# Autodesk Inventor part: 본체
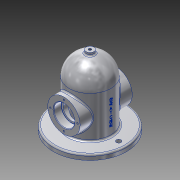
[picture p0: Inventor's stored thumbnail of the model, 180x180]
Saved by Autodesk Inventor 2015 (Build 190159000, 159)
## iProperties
Created: 2019-11
Part Number: 본체
Material: 알루미늄 6061
Document SubType Name: Modeling
Designer: 101020202
Density: 2.7 g/cm^3
Appearance: 알루미늄 - 평지
Author: 101020202
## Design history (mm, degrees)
sketch "스케치1"
  geometry: C1 r 70 at (0, 0); 1 further point
  constraints: 1 centre point, 1 coincident
  dimensions: "d0" = 140 diameter of C1
extrude "돌출1" new body sketch "스케치1" distance "d1" = 10; taper "d2" = 0 deg
sketch "스케치2"
  geometry: C1 r 70 at (0, 0) reference; C2 r 40 at (0, 0)
  constraints: 1 centre point, 1 coincident
  dimensions: "d3" = 80 diameter of C2
extrude "돌출2" join sketch "스케치2" distance "d4" = 120; taper "d5" = 0 deg
fillet "모깎기1" dims "d6" = 40
sketch "스케치3"
  geometry: L1 (-70, 0)-(-70, 10) reference; L2 (-70, 10)-(-40, 10) reference; L3 (-40, 10)-(-40, 90) reference; L4 (40, 90)-(40, 10) reference; L5 (40, 10)-(70, 10) reference; L6 (70, 10)-(70, 0) reference; L7 (70, 0)-(-70, 0) reference; C1 r 31 at (0, 50); A1 r 40 centre (0, 90) between (0, 130) and (-40, 90) reference; A2 r 40 centre (0, 90) between (40, 90) and (0, 130) reference; 2 further points
  constraints: 1 centre point, 1 midpoint, 1 vertical alignment
  dimensions: "d7" = 62 diameter of C1; "d8" = 50 distance of point (0, 0) C1.centre
extrude "돌출3" join sketch "스케치3" stored distance "d9" = 100; taper "d10" = 0 deg
sketch "스케치4"
  geometry: L1 (70, 10)-(70, 0) reference; L2 (70, 0)-(-70, 0) reference; L3 (-70, 0)-(-70, 10) reference; L4 (-70, 10)-(-40, 10) reference; L5 (-40, 10)-(-40, 19) reference; L6 (-40, 19)-(-50, 19) reference; L7 (-50, 19)-(-50, 81) reference; L8 (-50, 81)-(-40, 81) reference; L9 (-40, 81)-(-40, 90) reference; L10 (40, 90)-(40, 81) reference; L11 (40, 81)-(50, 81) reference; L12 (50, 81)-(50, 19) reference; L13 (50, 19)-(40, 19) reference; L14 (40, 19)-(40, 10) reference; L15 (40, 10)-(70, 10) reference; L16 (0, 0)-(30, 0); L17 (30, 0)-(30, 90); L18 (0, 120)-(0, 0); A1 r 40 centre (0, 90) between (40, 90) and (0, 130) reference; A2 r 40 centre (0, 90) between (0, 130) and (-40, 90) reference; A3 r 30 centre (0, 90) between (30, 90) and (0, 120)
  constraints: 6 end point, 2 point on circle, 1 centre point, 1 horizontal, 1 perpendicular, 1 vertical
  dimensions: "d11" = 30 radius of A3; "d12" = 10 distance between parallel lines of L10 L17; "d13" = 90 distance of L16.end L17.end; "d14" = 120 distance of L18.start L16.start
revolve "회전1" sketch "스케치4" stored, may be unused: angle "d15" = 90 deg
sketch "스케치5"
  geometry: C1 r 31 at (0, 0) reference; 1 further point
hole "구멍1" sketch "스케치5" at (0, 0) diameter "d16" = 33; stored, may be unused: countersink angle "d20" = 90 deg, drill point angle "d22" = 0 deg; dims "d17" = 6, "d18" = 40, "d19" = 15, "d21" = 40
sketch "스케치6"
  geometry: C1 r 20 at (0, 0) reference; 2 further points
  constraints: 1 vertical alignment
  dimensions: "d23" = 26 distance of C1.centre point (0, 26)
hole "구멍2" sketch "스케치6" at (0, 26) diameter "d24" = 3.242; stored, may be unused: countersink angle "d28" = 90 deg, drill point angle "d30" = 118 deg; dims "d25" = 8, "d26" = 40, "d27" = 15, "d29" = 10
node "작업 평면1"
sketch "스케치7"
  geometry: C1 r 7.5 at (0, 0); 1 further point
  constraints: 1 centre point, 1 coincident
  dimensions: "d35" = 15 diameter of C1
extrude "돌출4" join sketch "스케치7" stored distance "d36" = 100; taper "d37" = 0 deg
sketch "스케치8"
  geometry: C1 r 7.5 at (0, 0) reference
hole "구멍3" sketch "스케치8" at (0, 0) diameter "d38" = 5.188; stored, may be unused: countersink angle "d42" = 90 deg, drill point angle "d44" = 0 deg; dims "d39" = 12, "d40" = 40, "d41" = 15, "d43" = 12
sketch "스케치9"
  geometry: C1 r 40 at (0, 0) reference; C2 r 30 at (0, 0) reference; C3 r 40 at (0, 0) reference; C4 r 70 at (0, 0) reference; 2 further points
  constraints: 2 horizontal alignment
  dimensions: "d45" = 55 distance of C1.centre point (-55, 0); "d46" = 55 distance of C1.centre point (55, 0)
hole "구멍4" sketch "스케치9" at (-55, 0), (55, 0) diameter "d47" = 9; stored, may be unused: countersink angle "d51" = 90 deg, drill point angle "d53" = 0 deg; dims "d48" = 12, "d49" = 40, "d50" = 15, "d52" = 12
node "작업 평면2"
sketch "스케치10"
  geometry: L1 (-70, -10)-(70, -10) reference; 3 further points
  constraints: 1 midpoint, 1 vertical alignment, 1 other
  dimensions: "d54" = 50 distance from line of L1 point (0, 40)
feature "엠보싱1" sketch "스케치10" dims "d55" = 0.5, "d56" = 0
chamfer "모따기1" distance "d57" = 1; stored, may be unused: second distance "d58" = 2, angle "d59" = 45 deg
fillet "모깎기2" dims "d60" = 0.3
fillet "모깎기3" dims "d61" = 3
node "솔리드1"
mirror "대칭1"
pattern_circular "원형 패턴1" dims angle "d32" = 360 deg
mirror "대칭2"
node "절단 모서리 투영1"
node "절단 모서리 투영2"
node "절단 모서리 투영3"
other parameters: "d34" = 135
